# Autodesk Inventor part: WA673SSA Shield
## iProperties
Category: PARTsolutions
Created: 2011-07
Part Number: WA673SSA Shield
Catalog Web Link: www.cadenas.de
Description: Six types s - Metric system sizes
Document SubType Name: Modeling
Designer: PARTsolutions
Density: 1 g/cm^3
NB: WA673SSA Shield
NN: Six types s
NT: Metric system sizes
NBSYN: $ORDER. Shield
LINA: WA673SSA Shield
SD: 3.0
D: 6
B: 2.0
R: 0.08
ORDER: WA673SSA
CR: 242
COR: 94
CRF: 25
CORF: 9,5
LSG: 60 000
LSO: 71 000
MASS: 0.20
ORDER1: 673
D1: 7.2
D2: 7.2
C1: 0.6
C2: 0.6
WSS: WA673SSA
WDS: SSA
UTWF: FL673
FORSS: FLWA673SA
FORDS: SSA
DA1: 3,6
DA2: 4,1
DA: 5,4
RAS: 0,08
MASS1: 0.26
B1: 2.5
VERS: 3
X: 1.500
N: 9
O: 14.130
RB: 0.444
KT: DUMMY
SUPPLIER: NTN
ARTICLENO: WA673SSA Shield
BOMINFO: WA673SSA Shield
CREATOR: CADENAS GmbH
PSOL_IDENT_0: {\\10.0.0.251\ps_data\23d-libs\ntn\ball_roller_bearings\miniature_extra_small_bb\metric_system_sizes
PSOL_IDENT_1: \mss_s.prj},180 {VTYP=3D},{NB=WA673SSA Shield},{LINA=WA673SSA Shield},{NN=Six types s},{DATE=11.12.2
PSOL_IDENT_2: 007 08:48:24},{GEOMDATE=02.04.2007 12:30:00},{VERSION=},{LINEID=12590},{LINESUBID=-1},{WBVAR=}  {NB=
PSOL_IDENT_3: WA673SSA Shield},{LINA=WA673SSA Shield},{KT=DUMMY},{IDNR=},{SD=3.0},{D=6},{B=2.0},{R=0.08},{ORDER=WA
PSOL_IDENT_4: 673SSA},{CR=242},{COR=94},{CRF=25},{CORF=9,5},{LSG=60 000},{LSO=71 000},{MASS=0.20},{ORDER1=673},{D1
PSOL_IDENT_5: =7.2},{D2=7.2},{C1=0.6},{C2=0.6},{WSS=WA673SSA},{WDS=SSA},{UTWF=FL673},{FORSS=FLWA673SA},{FORDS=SSA}
PSOL_IDENT_6: ,{DA1=3,6},{DA2=4,1},{DA=5,4},{RAS=0,08},{MASS1=0.26},{B1=2.5},{VERS=3},{X=1.5},{N=9},{O=14.13},{RB=
PSOL_IDENT_7: 0.444}
Title: WA673SSA Shield
Author: Cadenas PARTsolutions
Comments: Metric system sizes
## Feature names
1. Revolution1
